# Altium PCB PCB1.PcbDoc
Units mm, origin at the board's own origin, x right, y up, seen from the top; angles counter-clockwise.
Board outline 152.4 x 101.6 mm, 2 copper layers (Top Layer, Bottom Layer); 27 components, 24 nets, 75 pads, 0 vias.
Unrouted connection lines stored in the file: 2.
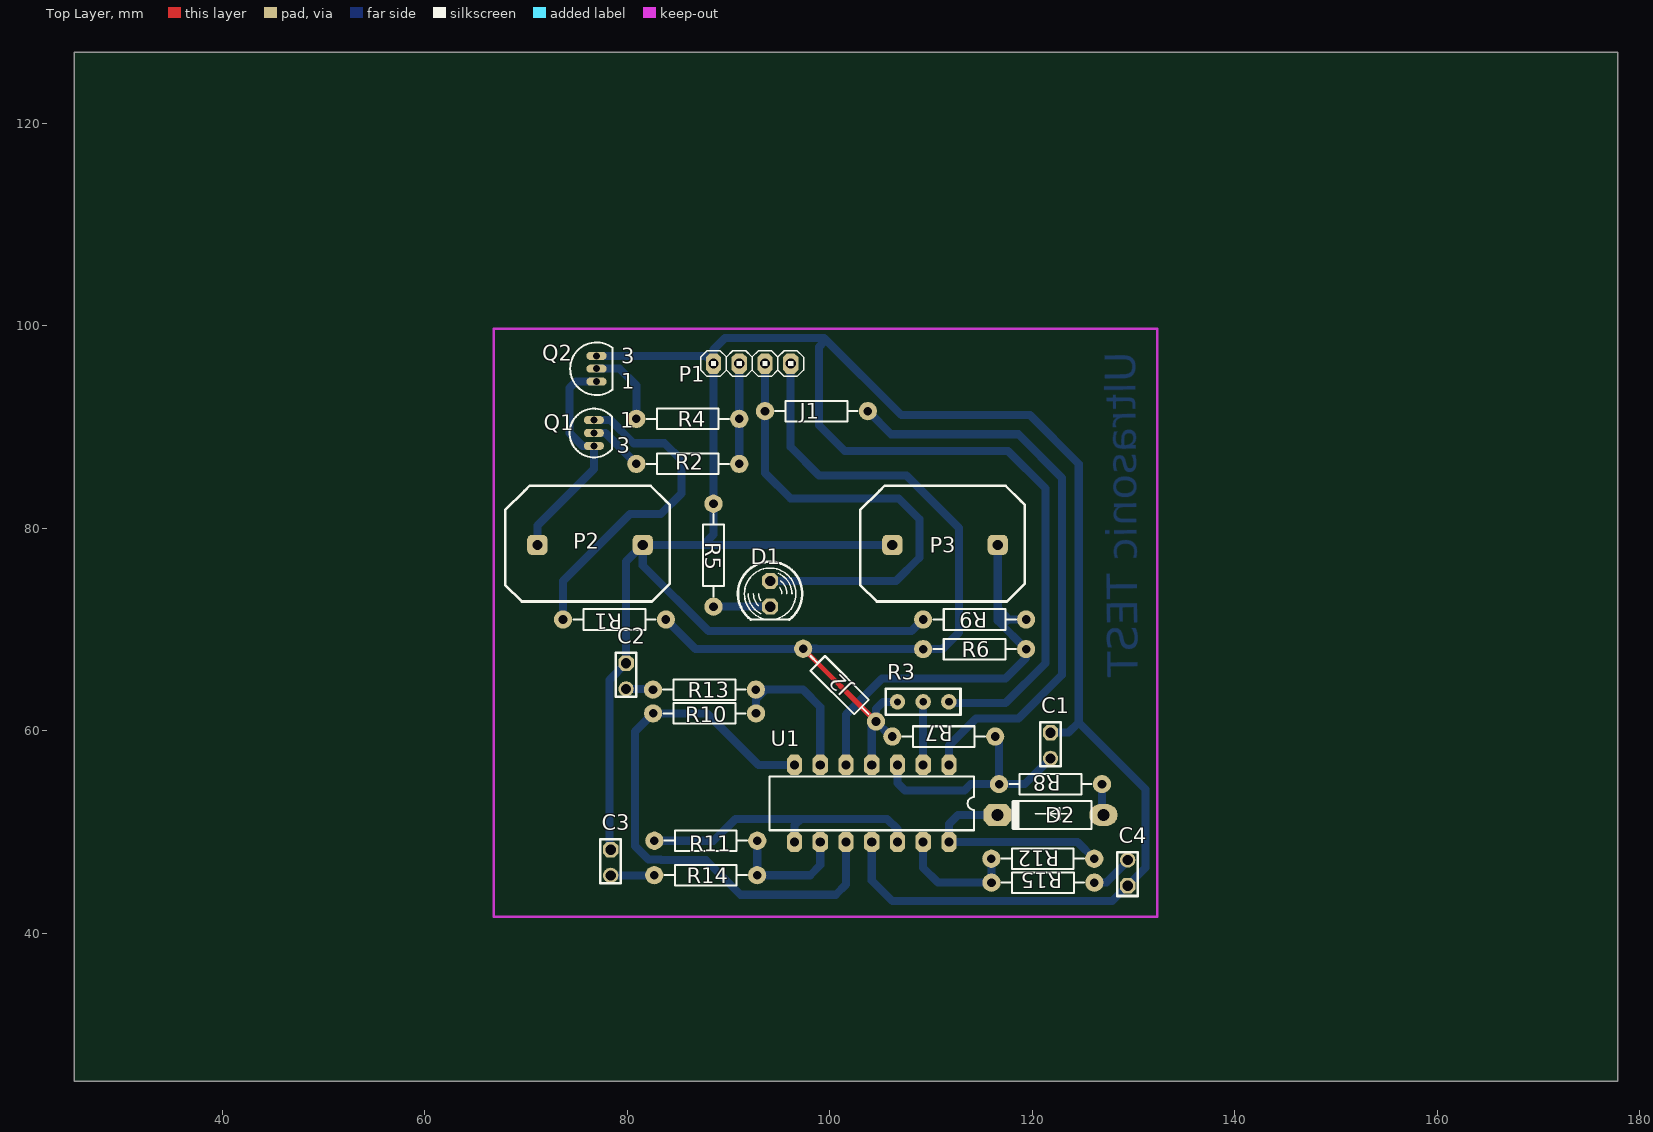
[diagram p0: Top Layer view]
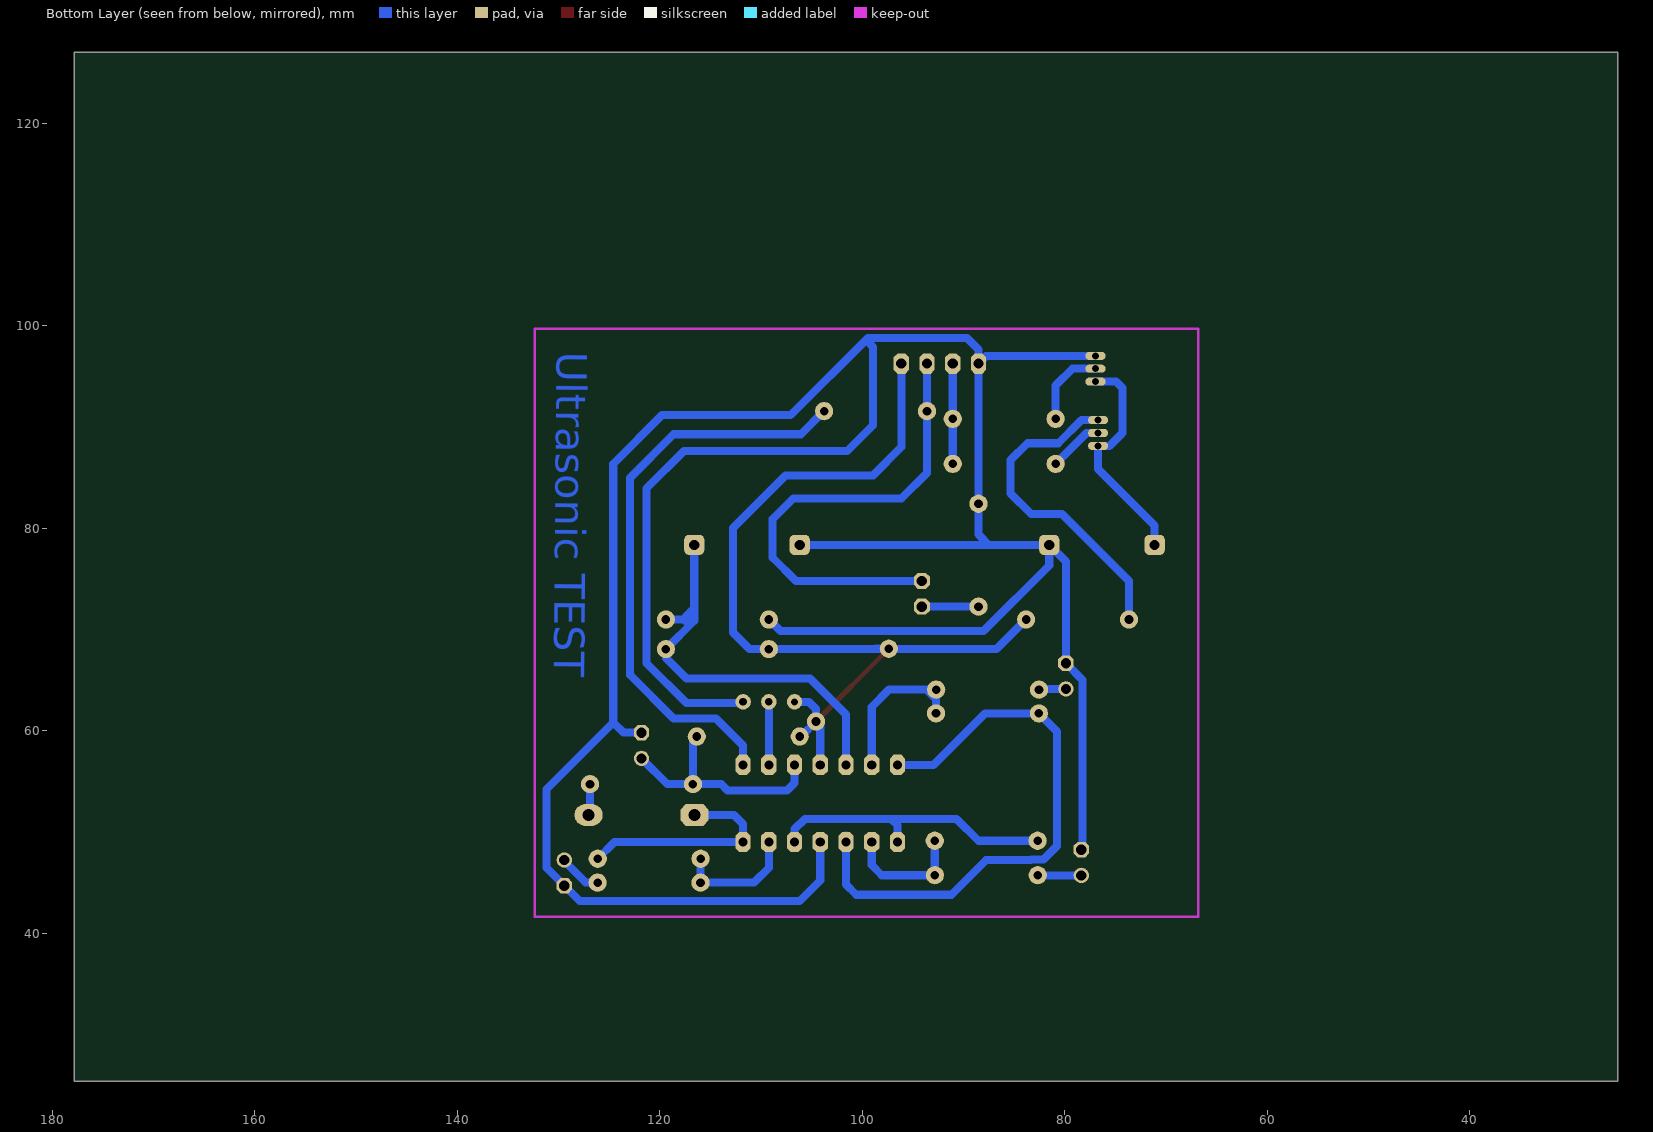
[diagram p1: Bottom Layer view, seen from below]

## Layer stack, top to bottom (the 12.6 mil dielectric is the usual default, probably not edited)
Top Layer: signal copper 0.0356
Dielectric: dielectric 0.32, FR-4, Dk 4.8
Bottom Layer: signal copper 0.0356

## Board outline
25.4,25.4 177.8,25.4 177.8,127 25.4,127

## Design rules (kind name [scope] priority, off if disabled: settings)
Clearance [All] p1: gap=0.254
PolygonConnect [All] p1: connectstyle=Relief reliefconductorwidth=0.254 reliefentries=4 polygonreliefangle="90 Angle"
RoomDefinition Sheet1 [InComponentClass('Sheet1')] p1: confinementstyle=ConfineIn formatcopy=TRUE lockcomponents=FALSE outline 178.562,24.793 184.277,24.793 184.277,38.354 178.562,38.354
RoutingLayers [All] p1: top layer_v5=FALSE bottom layer_v5=TRUE
RoutingVias [All] p1: holewidth=0.711 width=1.27 viastyle="Through Hole" minholewidth=0.711 minwidth=1.27 maxholewidth=0.711 maxwidth=1.27
SilkscreenOverComponentPads [All] p1: minsilkscreentomaskgap=0.254
SolderMaskExpansion [All] p1: expansion=0.102
Width [All] p1: maxlimit=0.8 minlimit=0.3 preferedwidth=0.5
26 further rules are at their usual default settings.

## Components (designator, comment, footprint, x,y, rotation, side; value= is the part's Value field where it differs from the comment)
C1 "Cap" My_cap100n 121.793,58.547 r270 top
C2 "Cap" My_cap100n 79.883,65.405 r270 top
C3 "Cap" My_cap100n 78.359,46.99 r270 top
C4 "Cap" My_cap100n 129.413,45.974 r90 top
D1 "LED" "LED 5mm" 94.107,73.533 r270 top
D2 "1N4007" My_DO-41 116.332,51.435 r0 top
J1 "Res Semi" "Res 0.4" 98.679,91.567 r0 top
J2 "Res Semi" "Res 0.4" 100.965,64.516 r315 top
P1 "Header 4" My_1X04 92.329,96.266 r0 top
Q1 "BC337-25" SOT54 76.708,89.408 r0 top
Q2 "BC327" 29-04 76.962,95.758 r0 top
R1 "Res Semi" "Res 0.4" 78.74,70.993 r180 top
R2 "Res Semi" "Res 0.4" 85.979,86.36 r0 top
R3 "RPot" multitran 105.918,61.595 r0 top
R4 "Res Semi" "Res 0.4" 85.979,90.805 r0 top
R5 "Res Semi" "Res 0.4" 88.519,77.343 r270 top
R6 "Res Semi" "Res 0.4" 114.3,68.072 r0 top
R7 "Res Semi" "Res 0.4" 111.252,59.436 r180 top
R8 "Res Semi" "Res 0.4" 121.793,54.737 r180 top
R9 "Res Semi" "Res 0.4" 114.3,70.993 r180 top
R10 "Res Semi" "Res 0.4" 87.63,61.722 r0 top
R11 "Res Semi" "Res 0.4" 87.757,49.149 r0 top
R12 "Res Semi" "Res 0.4" 121.031,47.371 r180 top
R13 "Res Semi" "Res 0.4" 87.618,64.067 r0 top
R14 "Res Semi" "Res 0.4" 87.745,45.744 r0 top
R15 "Res Semi" "Res 0.4" 121.043,45.007 r180 top
U1 "LM324AN" DIP14 104.14,52.832 r180 top

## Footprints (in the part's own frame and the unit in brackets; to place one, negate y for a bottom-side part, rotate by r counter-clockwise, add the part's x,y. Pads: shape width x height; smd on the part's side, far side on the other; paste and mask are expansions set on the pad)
29-04 [mm] "TO, Flat Index; 3 In-Line, Axial Leads; Body Dia. 4.8mm; Leads 0.48 x 0.5 mm (max)"
  oval 2x0.8 hole 0.7: 1(0,-1.27)
  oval 2x0.8 hole 0.7 paste+0: 2(0,0) 3(0,1.27)
  silkscreen extent -2.6,-2.6 1.6,2.6
DIP14 [mm] "DIP; 14 Leads; Row Spacing 7.62 mm; Pitch 2.54 mm"
  oct 1.5x2 hole 0.9: 1(-7.62,-3.81) 2(-5.08,-3.81) 3(-2.54,-3.81) 4(0,-3.81) 5(2.54,-3.81) 6(5.08,-3.81) 7(7.62,-3.81) 8(7.62,3.81) 9(5.08,3.81) 10(2.54,3.81) 11(0,3.81) 12(-2.54,3.81) 13(-5.08,3.81) 14(-7.62,3.81)
  silkscreen extent -10.1,-2.65 10.1,2.65
"LED 5mm" [mm]
  oct 1.6x1.6 hole 1.016: A(-1.27,0) K(1.27,0)
  silkscreen extent -3.17,-3.17 2.54,3.17
multitran [mil]
  round 60 hole 27.56: 1(30,50)
  round 60 hole 30: 2(130,50) 3(230,50)
  silkscreen extent -15,0 275,100
My_1X04 [mil]
  oct 60x80 hole 40: 1(-150,0) 2(-50,0) 3(50,0) 4(150,0)
  silkscreen extent -200,-50 200,50
My_cap100n [mil]
  oct 60x60 hole 40: 1(-50,0)
  round 60 hole 40: 2(50,0)
  silkscreen extent -90,-40 80,40
My_DO-41 [mil]
  oval 110x85 hole 47.24: A(420.71,10)
  oct 110x85 hole 47.24: K(8.9,10)
  silkscreen extent 64,-45 375,65
"Res 0.4" [mm]
  round 1.8 hole 0.85: 1(-5.08,0) 2(5.08,0)
  silkscreen extent -4.06,-1.02 4.06,1.02
SOT54 [mm] "TO, Flat Index; 3 In-Line, Axial Leads; Body Dia. 4.6mm; Leads 0.48 x 0.45 mm (max)"
  oval 2x0.8 hole 0.7 paste+0: 1(0,1.27) 2(0,0) 3(0,-1.27)
  silkscreen extent -2.4,-2.4 1.8,2.4

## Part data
C1 C2 C3 C4: library part "Cap ceramic", "CAP-100Nf"
D1: "Typical INFRARED GaAs LED"
D2: "1 Amp Diode"
J1 J2 R1 R2 R4 R5 R6 R7 R8 R9 R10 R11 R12 R13 R14 R15: "Semiconductor Resistor"
P1: "Header, 4-Pin"
Q1: "NPN General-purpose Transistor"
Q2: "Amplifier Transistor PNP Silicon"
R3: "Potentiometer"
U1: "Low-Power Quad Operational Amplifier"

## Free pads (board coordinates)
  rrect50% 2x2 hole 1: 1(81.534,78.359) 1(116.586,78.359) 2(71.12,78.359) 2(106.172,78.359)

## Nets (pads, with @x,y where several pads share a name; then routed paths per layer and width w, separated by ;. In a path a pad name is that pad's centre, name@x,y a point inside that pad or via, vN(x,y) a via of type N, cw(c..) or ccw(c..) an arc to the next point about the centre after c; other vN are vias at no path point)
GND: C1.1 C2.1 C3.1 C4.1 P1.1 pad.1@81.534,78.359 pad.2@106.172,78.359 Q2.3 R3.3 R5.1 R9.2 U1.11 | length 303.5
  Bottom Layer w0.8: Q2.3 87.757,97.028 P1.1 ; C3.1 78.232,48.387 78.232,65.024 C2.1 79.883,76.708 pad.1@81.534,78.359 ; U1.11 104.14,45.212 106.172,43.18 127.889,43.18 C4.1 131.191,46.482 131.191,54.229 124.587,60.833 ; pad.2@106.172,78.359 87.503,78.359 ; R9.2 108.077,69.85 88.011,69.85 81.534,76.327 pad.1@81.534,78.359 ; R3.3 111.887,62.738 117.348,62.738 121.285,66.675 121.285,83.947 117.602,87.63 101.473,87.63 98.933,90.17 98.933,97.917 99.441,98.425 99.441,98.806 ; C1.1 123.571,59.817 124.587,60.833 ; pad.1@81.534,78.359 87.503,78.359 ; 87.503,78.359 88.519,79.375 R5.1 P1.1 ; P1.1 88.519,97.663 89.662,98.806 99.441,98.806 ; 99.441,98.806 107.061,91.186 119.761,91.186 124.587,86.36 124.587,60.833
JAMP1: C1.2 R7.1 R8.2 U1.3 | length 23.4
  Bottom Layer w0.8: U1.3 106.68,54.864 107.442,54.102 113.284,54.102 113.919,54.737 R8.2 ; R7.1 116.713,59.055 R8.2 ; C1.2 119.253,54.737 R8.2
JAMP2: D1.A J1.1 P1.3 | length 47.4
  Bottom Layer w0.8: P1.3 J1.1 93.599,85.471 96.139,82.931 106.807,82.931 108.839,80.899 108.839,77.089 106.553,74.803 D1.A
NetC2_2: C2.2 R13.1 | length 2.7
  Bottom Layer w0.8: C2.2 82.47,64.135 R13.1
NetC3_2: C3.2 R14.1 | length 4.3
  Bottom Layer w0.8: C3.2 82.641,45.72 R14.1
NetC4_2: C4.2 R15.1 | length 4.3
  Bottom Layer w0.8: R15.1 127.303,45.007 129.413,47.117 C4.2
NetD1_K: D1.K R5.2 | length 5.6
  Bottom Layer w0.8: R5.2 D1.K
NetD2_A: D2.A R8.1 | length 3.1
  Bottom Layer w0.8: R8.1 126.873,51.834 D2.A
NetD2_K: D2.K R12.1 U1.14 | length 22
  Bottom Layer w0.8: D2.K 112.649,51.689 111.76,50.8 U1.14 124.46,49.022 R12.1
NetJ1_2: J1.2 U1.1 | length 57.3
  Bottom Layer w0.8: J1.2 106.045,89.281 118.618,89.281 122.936,84.963 122.936,65.532 118.618,61.214 114.427,61.214 111.76,58.547 U1.1
NetJ2_2:  | length 8.1
  Bottom Layer w0.8: 104.14,56.642 104.14,60.507 104.557,60.924 104.557,62.158 105.264,62.865 106.68,62.865
NetP1_2: P1.2 R2.2 R4.2 | length 9.9
  Bottom Layer w0.8: R2.2 R4.2 P1.2
NetP2_1: pad.2@71.12,78.359 Q1.3 Q2.1 | length 22.4
  Bottom Layer w0.8: pad.2@71.12,78.359 71.12,80.264 76.708,85.852 Q1.3 75.565,88.138 74.295,89.408 74.295,93.853 74.93,94.488 Q2.1
NetP3_2: pad.1@116.586,78.359 R6.2 R9.1 U1.5 | length 41.1
  Bottom Layer w0.8: U1.5 101.6,61.595 105.156,65.151 117.348,65.151 119.38,67.183 R6.2 116.586,70.866 116.586,72.136 ; pad.1@116.586,78.359 116.586,72.136 ; R9.1 117.602,70.993 117.411,70.802 117.411,71.31 116.586,72.136
NetQ1_1: Q1.1 R1.2 | length 32.6
  Bottom Layer w0.8: R1.2 73.66,74.803 80.264,81.407 83.312,81.407 85.344,83.439 85.344,86.741 83.693,88.392 80.645,88.392 78.359,90.678 Q1.1
NetQ1_2: Q1.2 R2.1 | length 5.5
  Bottom Layer w0.8: Q1.2 77.851,89.408 R2.1
NetQ2_2: Q2.2 R4.1 | length 7.9
  Bottom Layer w0.8: Q2.2 79.248,95.758 80.899,94.107 R4.1
NetR3_2: R3.2 U1.2 | length 6.2
  Bottom Layer w0.8: U1.2 R3.2
NetR10_1: R10.1 U1.7 U1.10 | length 58
  Bottom Layer w0.8: U1.7 92.964,56.642 87.884,61.722 R10.1 80.772,59.944 80.772,48.641 82.115,47.298 83.309,47.298 83.363,47.244 87.757,47.244 91.186,43.815 100.584,43.815 101.6,44.831 U1.10 U1.10@101.6,49.657
NetR10_2: R10.2 R13.2 U1.6 | length 16.5
  Bottom Layer w0.8: R13.2 93.658,64.067 ; R10.2 92.71,63.119 ; R13.2@92.71,64.055 92.71,63.119 ; U1.6 99.06,62.357 97.35,64.067 93.658,64.067 ; 92.71,63.119 93.658,64.067
NetR11_1: R11.1 U1.8 U1.12 | length 29.1
  Bottom Layer w0.8: R11.1 88.519,49.149 90.678,51.308 97.155,51.308 ; U1.8 96.52,50.673 97.155,51.308 ; U1.12 106.68,50.292 105.664,51.308 97.155,51.308
NetR11_2: R11.2 R14.2 U1.9 | length 11.3
  Bottom Layer w0.8: 92.837,48.133 92.837,45.756 R14.2 98.068,45.744 99.06,46.736 U1.9
NetR12_2: R12.2 R15.2 U1.13 | length 12.3
  Bottom Layer w0.8: U1.13 109.22,46.482 110.695,45.007 R15.2 115.963,47.359 R12.2
VCC: J2.1 J2.2 P1.4 R1.1 R3.1 R6.1 R7.2 U1.4 | length 82
  Top Layer w0.5: J2.1 J2.2
  Bottom Layer w0.8: R1.1 86.741,68.072 R6.1 111.125,68.072 112.776,69.723 112.776,80.01 107.569,85.217 98.933,85.217 96.139,88.011 P1.4 ; J2.1 98.643,68.108 ; 105.302,60.179 106.045,59.436 R7.2

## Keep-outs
Keep-Out Layer:
  lines w0.254: 66.802,41.656 132.334,41.656 132.334,99.695 66.802,99.695 66.802,41.656

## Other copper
Bottom Layer:
  text "Ultrasonic TEST" at 130.175,97.409 h3 r90.49

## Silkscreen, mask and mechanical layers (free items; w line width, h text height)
Top Overlay:
  lines w0.254: 67.945,74.422 67.945,81.788 69.85,83.693 70.358,84.201 80.391,84.201 82.296,84.201 83.82,82.677 84.201,82.296 84.201,74.549 82.423,72.771 69.596,72.771 67.945,74.422 ; 102.997,74.422 104.648,72.771 117.475,72.771 119.253,74.549 119.253,82.296 118.872,82.677 117.348,84.201 115.443,84.201 105.41,84.201 104.902,83.693 102.997,81.788 102.997,74.422
  text "P2" at 74.676,77.978 h1.52
  text "P3" at 109.855,77.597 h1.52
